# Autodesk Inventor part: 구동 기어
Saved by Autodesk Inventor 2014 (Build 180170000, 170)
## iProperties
Created: 2026-04
Part Number: 구동 기어
Material: 일반
Document SubType Name: Modeling
Designer: dg
Density: 1 g/cm^3
Appearance: 기본값
Author: dg
Author: jhkim
Creation Date: 2026-03-27
Sending System: Autodesk Inventor 2026
Preprocessor: ST-DEVELOPER v20.1
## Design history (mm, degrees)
node "구동 기어1"
node "솔리드1"
node "기준1"
